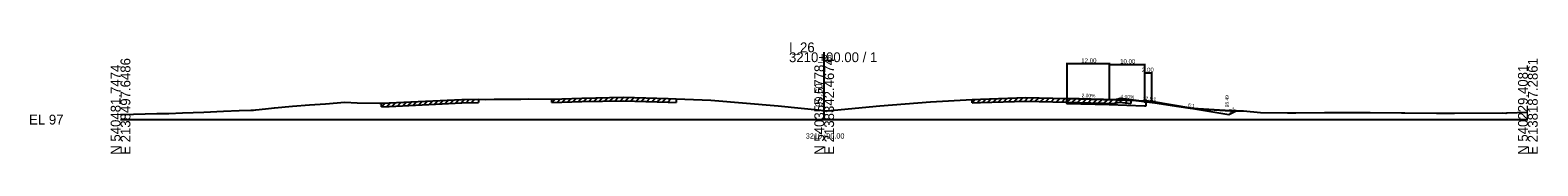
# Model space of a CAD drawing. Extents: x -13101 to 4803, y -924 to 22390.
# Drawn here: x 1974.3 to 2402.8, y 4990.3 to 5022 of the extents above; entities that cross this region are included whole.
import ezdxf

# ---------------------------------------------------------------- set-up
doc = ezdxf.new("R2010")
doc.units = 0
for name, color, linetype in [('RD_GPK_XS_Cell', 7, 'Continuous'), ('RD_XD_TX_Width', 7, 'Continuous'), ('RD_XS_Base', 7, 'Continuous'), ('RD_XS_EarthShd', 7, 'Continuous'), ('RD_XS_EwShp', 7, 'Continuous'), ('RD_XS_ExGround', 7, 'Continuous'), ('RD_XS_ExPaveRet', 7, 'Continuous'), ('RD_XS_OSBase', 7, 'Continuous'), ('RD_XS_Pave', 7, 'Continuous'), ('RD_XS_TieSlope', 7, 'Continuous'), ('RD_XS_TX_Baseline', 7, 'Continuous'), ('RD_XS_TX_Elev_EX', 7, 'Continuous'), ('RD_XS_TX_Elev_PR', 7, 'Continuous'), ('RD_XS_TX_ShdSlope', 7, 'Continuous'), ('RD_XS_TX_Slope', 7, 'Continuous'), ('RD_XS_TX_Station', 7, 'Continuous')]:
    doc.layers.add(name, color=color, linetype=linetype)

msp = doc.modelspace()

# ---------------------------------------------------------------- linework, layer by layer
at = {"layer": 'RD_GPK_XS_Cell'}
for p, q in [((2200, 5000), (2200, 5019.13)), ((2000, 5000), (2200, 5000)), ((2200, 5000), (2400, 5000))]:
    msp.add_line(p, q, dxfattribs=at)
at = {"layer": 'RD_XD_TX_Width'}
for p, q in [((2269, 5016.11), (2269, 5006.16)), ((2269, 5015.91), (2281, 5015.91)), ((2281, 5016.11), (2281, 5005.92)), ((2281, 5015.87), (2281, 5005.92)), ((2281, 5015.67), (2291, 5015.67)), ((2291, 5015.87), (2291, 5005.52)), ((2291, 5013.47), (2291, 5005.52)), ((2291, 5013.27), (2293, 5013.27)), ((2293, 5013.47), (2293, 5005.36))]:
    msp.add_line(p, q, dxfattribs=at)
at = {"layer": 'RD_XS_Base'}
for p, q in [((2269, 5004.56), (2281, 5004.32)), ((2281, 5004.32), (2291, 5003.92))]:
    msp.add_line(p, q, dxfattribs=at)
at = {"layer": 'RD_XS_EarthShd'}
msp.add_line((2291, 5005.32), (2293, 5005.16), dxfattribs=at)
at = {"layer": 'RD_XS_EwShp'}
for points in [[(2291.5, 5003.9), (2291.5, 5004.9), (2291, 5004.92), (2291, 5005.11), (2284.82, 5005.89), (2284.08, 5005.98), (2283.58, 5005.82), (2282.97, 5005.74), (2282.86, 5005.59), (2269, 5005.95), (2269, 5005.56), (2269, 5004.56), (2281, 5004.32), (2291, 5003.92)], [(2291, 5005.11), (2293.97, 5004.73), (2300.15, 5003.79), (2303.98, 5003.25), (2304.79, 5003.19), (2293, 5005.16), (2291, 5005.32)], [(2315, 5001.49), (2317.08, 5002.53), (2316.3, 5002.53), (2315.58, 5002.53), (2313.99, 5002.57), (2310.83, 5002.78), (2304.79, 5003.19)]]:
    msp.add_lwpolyline(points, close=True, dxfattribs=at)
at = {"layer": 'RD_XS_ExGround'}
msp.add_lwpolyline([(2000, 5001.45), (2000.51, 5001.46), (2003.69, 5001.55), (2010.3, 5001.75), (2013.7, 5001.78), (2017.6, 5001.89), (2023.71, 5002.08), (2029.29, 5002.41), (2033.72, 5002.61), (2037.05, 5002.67), (2037.79, 5002.65), (2038.48, 5002.75), (2041.24, 5003.03), (2043.73, 5003.35), (2048.83, 5003.8), (2053.74, 5004.24), (2058.27, 5004.48), (2063.75, 5004.95), (2067.24, 5004.74), (2073.61, 5004.66), (2074.2, 5004.63), (2076.37, 5004.75), (2097.04, 5005.73), (2101.76, 5005.82), (2103.79, 5005.72), (2106.2, 5005.79), (2113.8, 5005.83), (2116.02, 5005.86), (2122.56, 5005.82), (2131.15, 5006.11), (2142.91, 5006.38), (2155.68, 5005.97), (2157.89, 5005.9), (2167.74, 5005.5), (2186.87, 5003.9), (2200, 5002.6), (2200.88, 5002.51), (2215.85, 5003.94), (2230.17, 5005.01), (2242.01, 5005.76), (2244.46, 5005.85), (2257.34, 5006.27), (2268.73, 5005.96), (2282.86, 5005.59), (2282.97, 5005.74), (2283.58, 5005.82), (2284.08, 5005.98), (2284.82, 5005.89), (2293.97, 5004.73), (2300.15, 5003.79), (2303.98, 5003.25), (2310.83, 5002.78), (2313.99, 5002.57), (2315.58, 5002.53), (2316.3, 5002.53), (2318.72, 5002.53), (2319.22, 5002.48), (2324, 5002.05), (2331.68, 5001.96), (2334.01, 5001.9), (2342.22, 5002), (2344.02, 5002.01), (2345.75, 5002.05), (2354.03, 5002.05), (2355.18, 5002.01), (2364.04, 5001.92), (2365.07, 5001.89), (2374.05, 5001.84), (2379.15, 5001.81), (2392.83, 5001.89), (2393.74, 5001.87), (2394.07, 5001.88), (2400, 5002.07)], dxfattribs=at)
at = {"layer": 'RD_XS_ExPaveRet'}
for p, q in [((2086.2, 5004.21), (2087.25, 5005.26)), ((2087.7, 5004.28), (2088.75, 5005.33)), ((2089.2, 5004.35), (2090.25, 5005.4)), ((2090.7, 5004.43), (2091.75, 5005.48)), ((2092.2, 5004.5), (2093.25, 5005.55)), ((2093.7, 5004.57), (2094.75, 5005.62)), ((2095.2, 5004.64), (2096.25, 5005.69)), ((2096.7, 5004.71), (2097.73, 5005.74)), ((2098.2, 5004.75), (2099.22, 5005.77)), ((2099.7, 5004.78), (2100.72, 5005.8)), ((2101.76, 5005.82), (2101.76, 5004.82)), ((2122.56, 5004.82), (2123.59, 5005.86)), ((2122.56, 5004.82), (2122.56, 5005.82)), ((2124.06, 5004.87), (2125.09, 5005.91)), ((2125.56, 5004.92), (2126.59, 5005.96)), ((2127.06, 5004.97), (2128.09, 5006.01)), ((2128.56, 5005.02), (2129.59, 5006.06)), ((2130.06, 5005.07), (2131.09, 5006.11)), ((2131.15, 5005.11), (2142.91, 5005.38)), ((2131.56, 5005.12), (2132.58, 5006.14)), ((2133.06, 5005.15), (2134.08, 5006.18)), ((2134.56, 5005.19), (2135.58, 5006.21)), ((2136.06, 5005.22), (2137.08, 5006.25)), ((2137.56, 5005.26), (2138.58, 5006.28)), ((2139.06, 5005.29), (2140.08, 5006.31)), ((2140.56, 5005.32), (2141.58, 5006.35)), ((2142.06, 5005.36), (2143.07, 5006.37)), ((2142.91, 5005.38), (2155.68, 5004.97)), ((2143.56, 5005.36), (2144.53, 5006.33)), ((2145.06, 5005.31), (2146.03, 5006.28)), ((2146.56, 5005.26), (2147.53, 5006.23)), ((2148.06, 5005.21), (2149.03, 5006.18)), ((2149.56, 5005.17), (2150.53, 5006.14)), ((2151.06, 5005.12), (2152.03, 5006.09)), ((2152.56, 5005.07), (2153.53, 5006.04)), ((2154.06, 5005.02), (2155.03, 5005.99)), ((2155.56, 5004.98), (2156.53, 5005.95)), ((2157.89, 5005.9), (2157.89, 5004.9)), ((2242.01, 5004.76), (2243.05, 5005.8)), ((2242.01, 5004.76), (2242.01, 5005.76)), ((2243.51, 5004.81), (2244.55, 5005.85)), ((2244.46, 5004.85), (2257.34, 5005.27)), ((2245.01, 5004.87), (2246.04, 5005.9)), ((2246.51, 5004.92), (2247.54, 5005.95)), ((2248.01, 5004.97), (2249.04, 5006)), ((2249.51, 5005.01), (2250.54, 5006.05)), ((2251.01, 5005.06), (2252.04, 5006.1)), ((2252.51, 5005.11), (2253.54, 5006.15)), ((2254.01, 5005.16), (2255.04, 5006.19)), ((2255.51, 5005.21), (2256.54, 5006.24)), ((2257.01, 5005.26), (2258, 5006.25)), ((2257.34, 5005.27), (2268.73, 5004.96)), ((2258.51, 5005.24), (2259.48, 5006.21)), ((2260.01, 5005.2), (2260.98, 5006.17)), ((2261.51, 5005.16), (2262.48, 5006.13)), ((2263.01, 5005.12), (2263.98, 5006.09)), ((2264.51, 5005.08), (2265.48, 5006.05)), ((2266.01, 5005.04), (2266.98, 5006.01)), ((2267.51, 5004.99), (2268.48, 5005.97)), ((2269.01, 5004.95), (2269.98, 5005.93)), ((2270.51, 5004.91), (2271.48, 5005.89)), ((2272.01, 5004.87), (2272.98, 5005.85)), ((2273.51, 5004.84), (2274.48, 5005.81)), ((2275.01, 5004.8), (2275.98, 5005.77)), ((2276.51, 5004.76), (2277.48, 5005.73)), ((2278.01, 5004.72), (2278.98, 5005.69)), ((2279.51, 5004.68), (2280.48, 5005.65)), ((2281.01, 5004.64), (2281.98, 5005.61)), ((2282.51, 5004.6), (2283.81, 5005.9)), ((2284.01, 5004.96), (2284.92, 5005.87)), ((2285.51, 5004.8), (2286.4, 5005.69)), ((2287.2, 5005.59), (2287.2, 5004.59)), ((2074.2, 5003.63), (2075.26, 5004.69)), ((2074.2, 5003.63), (2074.2, 5004.63)), ((2074.2, 5003.63), (2076.37, 5003.75)), ((2075.7, 5003.71), (2076.76, 5004.76)), ((2076.37, 5003.75), (2097.04, 5004.73)), ((2077.2, 5003.79), (2078.25, 5004.84)), ((2078.7, 5003.86), (2079.75, 5004.91)), ((2080.2, 5003.93), (2081.25, 5004.98)), ((2081.7, 5004), (2082.75, 5005.05)), ((2083.2, 5004.07), (2084.25, 5005.12)), ((2084.7, 5004.14), (2085.75, 5005.19)), ((2097.04, 5004.73), (2101.76, 5004.82)), ((2122.56, 5004.82), (2131.15, 5005.11)), ((2155.68, 5004.97), (2157.89, 5004.9)), ((2242.01, 5004.76), (2244.46, 5004.85)), ((2268.73, 5004.96), (2282.86, 5004.59)), ((2282.86, 5004.59), (2282.97, 5004.74)), ((2282.97, 5004.74), (2283.58, 5004.82)), ((2283.58, 5004.82), (2284.08, 5004.98)), ((2284.08, 5004.98), (2284.82, 5004.89)), ((2284.82, 5004.89), (2287.2, 5004.59))]:
    msp.add_line(p, q, dxfattribs=at)
at = {"layer": 'RD_XS_OSBase'}
for p, q in [((2269, 5005.56), (2269, 5005.96)), ((2269, 5004.56), (2269, 5005.56)), ((2291, 5004.92), (2291, 5005.32)), ((2291.5, 5004.9), (2291, 5004.92)), ((2291, 5003.92), (2291.5, 5003.9)), ((2291.5, 5003.9), (2291.5, 5004.9))]:
    msp.add_line(p, q, dxfattribs=at)
at = {"layer": 'RD_XS_Pave'}
for p, q in [((2269, 5005.96), (2281, 5005.72)), ((2281, 5005.72), (2291, 5005.32))]:
    msp.add_line(p, q, dxfattribs=at)
at = {"layer": 'RD_XS_TieSlope'}
for p, q in [((2293, 5005.16), (2315, 5001.49)), ((2315, 5001.49), (2317.08, 5002.53))]:
    msp.add_line(p, q, dxfattribs=at)

# ---------------------------------------------------------------- texts
at = {"layer": 'RD_GPK_XS_Cell'}
for s, p in [('3210+00.00 / 1', (2190, 5016.33)), ('I_26', (2190, 5019.13)), ('EL 97', (1974, 4998.6))]:
    msp.add_text(s, height=2.8, dxfattribs=at).set_placement(p)
for s, p in [('N 540481.7474', (2000, 4990)), ('E 2138497.6486', (2002.8, 4990)), ('N 540355.5778', (2200, 4990)), ('E 2138342.4674', (2202.8, 4990)), ('N 540229.4081', (2400, 4990)), ('E 2138187.2861', (2402.8, 4990))]:
    msp.add_text(s, height=2.8, rotation=90, dxfattribs=at).set_placement(p)
at = {"layer": 'RD_XD_TX_Width'}
for s, p in [('12.00', (2273.07, 5016.16)), ('10.00', (2284.11, 5015.92)), ('2.00', (2290.31, 5013.52))]:
    msp.add_text(s, height=1.25, dxfattribs=at).set_placement(p)
at = {"layer": 'RD_XS_TX_Baseline'}
msp.add_text('I_26', height=1.75, dxfattribs=at).set_placement((2197.6, 5016.6))
at = {"layer": 'RD_XS_TX_Elev_EX'}
msp.add_text('99.60', height=2, rotation=90, dxfattribs=at).set_placement((2199.5, 5003.6))
at = {"layer": 'RD_XS_TX_Elev_PR'}
msp.add_text('98.49', height=1, rotation=90, dxfattribs=at).set_placement((2315, 5003.49))
at = {"layer": 'RD_XS_TX_ShdSlope'}
msp.add_text('12.5:1', height=1, rotation=355.4261, dxfattribs=at).set_placement((2290.51, 5005.61))
msp.add_text('12.5:1', height=1, rotation=355.4261, dxfattribs=at).set_placement((2290.51, 5005.61))
at = {"layer": 'RD_XS_TX_Slope'}
for s, rotation, p in [('2.00%', 358.8542, (2273.16, 5006.37)), ('4.00%', 357.7094, (2284.22, 5006.09)), ('6:1', 350.5377, (2303.35, 5003.69)), ('2:1', 26.5651, (2315.26, 5001.9))]:
    msp.add_text(s, height=1, rotation=rotation, dxfattribs=at).set_placement(p)
at = {"layer": 'RD_XS_TX_Station'}
msp.add_text('3210+00.00', height=1.5, dxfattribs=at).set_placement((2194.76, 4994.6))

doc.saveas('drawing.dxf')
